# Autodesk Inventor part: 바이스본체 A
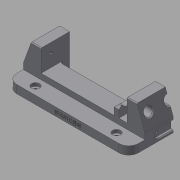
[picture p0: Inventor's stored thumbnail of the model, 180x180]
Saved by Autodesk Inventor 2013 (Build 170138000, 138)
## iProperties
Created: 2017-04
Part Number: 바이스본체 A
Material: 일반
Document SubType Name: Modeling
Designer: mduedu
Density: 1 g/cm^3
Author: mduedu
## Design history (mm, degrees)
sketch "스케치1"
  geometry: L1 (-75, 0)-(75, 0); L2 (-75, 0)-(-75, 17); L3 (-53, 17)-(53, 17); L4 (75, 17)-(75, 0); L5 (-75, 17)-(-65.173, 44); L6 (-65.173, 44)-(-53, 44); L7 (-53, 44)-(-53, 17); L8 (0, 0)-(0, 17); L9 (75, 17)-(65.173, 44); L10 (65.173, 44)-(53, 44); L11 (53, 44)-(53, 17); 1 further point
  constraints: 22 end point, 4 perpendicular, 2 horizontal alignment, 2 midpoint, 2 symmetric about line, 1 coincident, 1 collinear, 1 horizontal, 1 vertical
  dimensions: "d0" = 150 distance of L1.start L1.end; "d1" = 17 distance of L1.start L2.end; "d2" = 27 distance of L3.start L6.end; "d3" = 22 distance of L3.start L2.end; "d4" = 70 deg angle of L3 L5; "d54" = 20 deg angle of L9 L4
extrude "돌출1" new body sketch "스케치1" stored distance "d5" = 70; taper "d6" = 0 deg
sketch "스케치2"
  geometry: L1 (0, 70)-(106, 70) reference; L2 (106, 70)-(106, 0) reference; L3 (106, 0)-(0, 0) reference; L4 (0, 47)-(106, 47); L5 (106, 47)-(106, 23); L6 (106, 23)-(0, 23); L7 (0, 23)-(0, 47); L8 (0, 70)-(0, 0) reference; 2 further points
  constraints: 8 end point, 2 parallel, 2 point on line, 1 horizontal, 1 horizontal alignment, 1 midpoint, 1 perpendicular
  dimensions: "d7" = 24 distance between parallel lines of L6 L4
extrude "돌출2" cut sketch "스케치2" stored distance "d9" = 70; taper "d10" = 0 deg
sketch "스케치3"
  geometry: L1 (22, -23)-(128, -23) reference; L2 (128, -47)-(22, -47) reference; L3 (22, -18)-(128, -18); L4 (128, -52)-(22, -52); L5 (22, -18)-(22, -52); L6 (128, -18)-(128, -52); 1 further point
  constraints: 8 end point, 3 parallel, 2 point on line, 1 perpendicular
  dimensions: "d11" = 5 distance between parallel lines of L3 L1; "d12" = 5 distance between parallel lines of L4 L2
extrude "돌출3" cut sketch "스케치3" distance "d13" = 12; taper "d14" = 0 deg
fillet "모깎기1" dims "d15" = 3, "d16" = 3
sketch "스케치4"
  geometry: L1 (103, 23)-(3, 23) reference; L2 (0, 26)-(0, 0) reference; L3 (106, 0)-(0, 0) reference; L4 (106, 26)-(106, 0) reference; L5 (96, 0)-(90, 0); L6 (90, 0)-(90, 19.5); L7 (96, 19.5)-(96, 0); L8 (90, 19.5)-(96, 19.5); A1 r 3 centre (3, 26) between (0, 26) and (3, 23) reference; A2 r 3 centre (103, 26) between (103, 23) and (106, 26) reference; 1 further point
  constraints: 8 end point, 2 perpendicular, 1 horizontal, 1 parallel, 1 point on line
  dimensions: "d17" = 10 distance between parallel lines of L7 L4; "d18" = 6 distance between parallel lines of L7 L6; "d27" = 3.5 distance between parallel lines of L8 L1
extrude "돌출4" join sketch "스케치4" distance "d19" = 12; taper "d20" = 0 deg
chamfer "모따기1" distance "d21" = 3; stored, may be unused: second distance "d22" = 2, angle "d23" = 45 deg
chamfer "모따기2" distance "d24" = 3; stored, may be unused: second distance "d25" = 2, angle "d26" = 45 deg
sketch "스케치5"
  geometry: L1 (-15.5, 35.8)-(-15.5, -25.8) reference; L2 (19.5, 0)-(0, 0) reference; C1 r 6.5 at (9.5, 15); 1 further point
  constraints: 1 centre point
  dimensions: "d28" = 13 diameter of C1; "d30" = 15 distance from line of C1.centre L2; "d31" = 25 distance from line of C1.centre L1
extrude "돌출5" cut sketch "스케치5" stored distance "d32" = 12; taper "d33" = 0 deg
sketch "스케치6"
  geometry: C1 r 5 at (-10, 15); C2 r 5 at (-60, 15); A1 r 6.5 centre (-10, 15) between (-15.766, 12) and (-4.234, 12) reference; A2 r 6.5 centre (-60, 15) between (-65.766, 12) and (-54.234, 12) reference; 1 further point
  constraints: 2 centre point, 2 coincident
  dimensions: "d34" = 10 diameter of C1; "d35" = 10 diameter of C2 (= d34)
extrude "돌출6" cut sketch "스케치6" stored distance "d36" = 12; taper "d37" = 0 deg
chamfer "모따기3" distance "d38" = 1; stored, may be unused: second distance "d39" = 2, angle "d40" = 45 deg
chamfer "모따기4" distance "d41" = 1; stored, may be unused: second distance "d42" = 2, angle "d43" = 45 deg
sketch "스케치7"
  geometry: L1 (-35, 35.8)-(-35, -25.8) reference; L2 (-70, 0)-(0, 0) reference; C1 r 5 at (-35, 15); 1 further point
  constraints: 1 centre point, 1 point on line
  dimensions: "d44" = 10 diameter of C1; "d45" = 15 distance from line of C1.centre L2
extrude "돌출7" cut sketch "스케치7" stored distance "d46" = 12; taper "d47" = 0 deg
chamfer "모따기5" distance "d48" = 1; stored, may be unused: second distance "d49" = 2, angle "d50" = 45 deg
node "작업축1"
sketch "스케치8"
  geometry: L1 (-105, 32)-(105, 32) reference; L2 (58, 32)-(64, 32); L3 (64, 32)-(64, 40); L4 (64, 40)-(58, 40); L5 (58, 40)-(58, 32); L6 (53, 38)-(53, 26) reference; 1 further point
  constraints: 8 end point, 2 parallel, 1 horizontal, 1 perpendicular, 1 point on line
  dimensions: "d51" = 5 distance from line of L6 L2.start; "d52" = 6 distance of L3.end L4.end; "d53" = 16 diameter of L4 L1
revolve "회전1" sketch "스케치8" stored, may be unused: angle "d55" = 90 deg
fillet "모깎기2"
chamfer "모따기6" distance "d56" = 1; stored, may be unused: second distance "d57" = 2, angle "d58" = 45 deg
sketch "스케치9"
  geometry: L1 (17.5, 3)-(52.5, 3); L2 (52.5, 13)-(17.5, 13); L3 (70, 0)-(0, 0) reference; L4 (17.5, 8)-(52.5, 8); A1 r 5 centre (17.5, 8) between (17.5, 13) and (17.5, 3); A2 r 5 centre (52.5, 8) between (52.5, 3) and (52.5, 13); 3 further points
  constraints: 6 end point, 4 point on circle, 3 tangent, 2 centre point, 2 midpoint, 2 parallel, 1 horizontal, 1 vertical alignment
  dimensions: "d59" = 35 distance of L4.start L4.end; "d61" = 5 radius of A2; "d62" = 8 distance between parallel lines of L3 L4
extrude "돌출8" cut sketch "스케치9" distance "d63" = 3; taper "d64" = 0 deg
chamfer "모따기7" distance "d65" = 1; stored, may be unused: second distance "d66" = 2, angle "d67" = 45 deg
chamfer "모따기8" distance "d68" = 1; stored, may be unused: second distance "d69" = 2, angle "d70" = 45 deg
feature "분할1"
sketch "스케치10"
  geometry: L1 (35, 27)-(0, 27) reference; L2 (0, 0)-(0, 27) reference; 1 further point
  dimensions: "d85" = 11.5 distance from line of point (12, 15.5) L1; "d86" = 12 distance from line of point (12, 15.5) L2
hole "구멍1" sketch "스케치10" at (12, 15.5) diameter "d71" = 3.242; stored, may be unused: countersink angle "d75" = 90 deg, drill point angle "d77" = 120 deg; dims "d72" = 6, "d73" = 4, "d74" = 2, "d76" = 8
sketch "스케치11"
  geometry: A1 r 5 centre (17.5, 8) between (17.5, 13) and (17.5, 3) reference; 1 further point
  constraints: 1 coincident
hole "구멍3" sketch "스케치11" at (17.5, 8) diameter "d78" = 2.459; stored, may be unused: countersink angle "d82" = 90 deg, drill point angle "d84" = 120 deg; dims "d79" = 4.5, "d80" = 4, "d81" = 2, "d83" = 6
sketch "스케치13"
  geometry: L1 (75, 0)-(75, 35) reference; L2 (-75, 0)-(-75, 35) reference; L3 (-75, 35)-(75, 35); L4 (75, 35)-(75, 55); L5 (75, 55)-(-75, 55); L6 (-75, 55)-(-75, 35); 1 further point
  constraints: 8 end point, 2 parallel, 1 horizontal, 1 perpendicular, 1 point on line
  dimensions: "d90" = 20 distance between parallel lines of L5 L3; "d94" = 150 distance of L4.end L5.end (derived)
extrude "돌출9" join sketch "스케치13" distance "d92" = 10; taper "d93" = 0 deg
sketch "스케치14"
  geometry: L1 (-75, -35)-(-75, -55) reference; L2 (75, -55)-(75, -35) reference; L3 (-75, -45)-(75, -45); 3 further points
  constraints: 2 end point, 2 midpoint, 2 point on line
  dimensions: "d95" = 50 horizontal distance of point (-50, -45) point (0, 0); "d96" = 100 distance of point (50, -45) point (-50, -45)
fillet "모깎기3" dims "d97" = 12
chamfer "모따기9" distance "d98" = 1; stored, may be unused: second distance "d99" = 2, angle "d100" = 45 deg
hole "구멍4" sketch "스케치14" diameter "d101" = 4.134; stored, may be unused: countersink angle "d105" = 90 deg, drill point angle "d107" = 118 deg; dims "d102" = 6, "d103" = 10, "d104" = 4, "d106" = 8
sketch "스케치15"
  geometry: L1 (0, 0)-(126, 0) reference; 3 further points
  constraints: 1 midpoint, 1 vertical alignment, 1 other
  dimensions: "d109" = 5 distance from line of point (63, 5) L1
feature "엠보싱2" sketch "스케치15" dims "d0" = 150, "d1" = 17, "d2" = 27, "d3" = 22, "d4" = 70 deg, "d54" = 20 deg, "d110" = 0.5, "d111" = 0
node "솔리드1"
mirror "대칭1"
mirror "대칭2"
mirror "대칭3"
mirror "대칭4"
node "투영된 루프1"
